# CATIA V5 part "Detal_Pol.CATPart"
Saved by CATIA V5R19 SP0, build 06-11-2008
Part number: Part1
Bounding box of the stored display mesh (mm): x 0 to 195.834, y 0 to 172.681, z 0 to 100
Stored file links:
  E:\Podręcznik\catia\Machine\Detal_Pol.CATPart
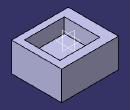
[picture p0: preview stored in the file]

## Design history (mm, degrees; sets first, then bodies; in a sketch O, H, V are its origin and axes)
Body1 (main body)
  Sketch1 on xy-plane, origin (0, 0, 0), H (1, 0, 0), V (0, 1, 0)
    line L1 (0, 0) -> (195.834, 0)
    line L2 (195.834, 0) -> (195.834, 172.6812)
    line L3 (195.834, 172.6812) -> (0, 172.6812)
    line L4 (0, 172.6812) -> (0, 0)
    horizontal: L1 H, L3 H
    vertical: L2 V, L4 V
  Pad1: profile Sketch1, direction (0, 0, 1), length 100
  Sketch2 on end face of Pad1, origin (0, 0, 100), H (1, 0, 0), V (0, 1, 0)
    line L1 (35.515, 143.7901) -> (172.6694, 143.7901)
    line L2 (172.6694, 143.7901) -> (172.6694, 21.7303)
    line L3 (172.6694, 21.7303) -> (35.515, 21.7303)
    line L4 (35.515, 21.7303) -> (35.515, 143.7901)
    horizontal: L1 H, L3 H
    vertical: L2 V, L4 V
  Pocket1: profile Sketch2, direction (0, 0, -1), length 50
Body2 "Polfabrykat"
  Sketch3 on start face of Pad1, origin (0, 0, 0), H (1, 0, 0), V (0, -1, 0)
    line L1 (0.1596, -0.2821) -> (195.8799, -0.2821)
    line L2 (195.8799, -0.2821) -> (195.8799, -172.2635)
    line L3 (195.8799, -172.2635) -> (0.1596, -172.2635)
    line L4 (0.1596, -172.2635) -> (0.1596, -0.2821)
    horizontal: L1 H, L3 H
    vertical: L2 V, L4 V
  Pad2: profile Sketch3, direction (0, 0, 1), length 100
